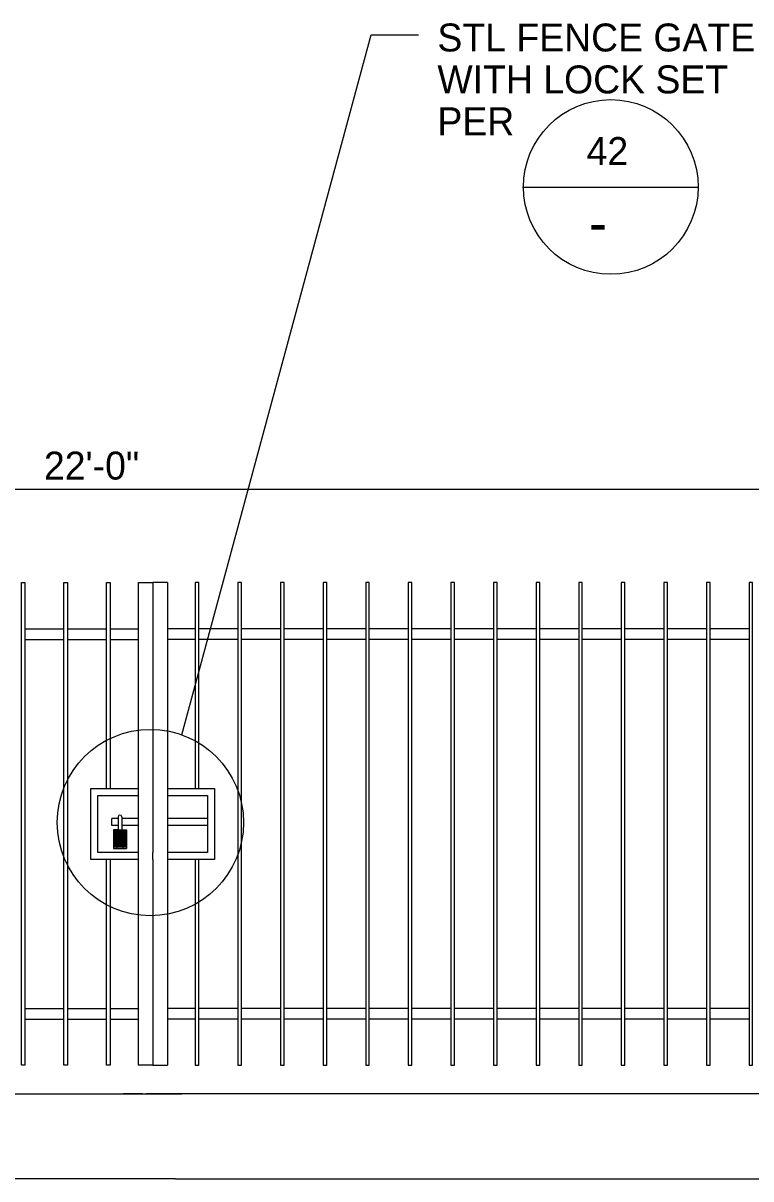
# Model space of a CAD drawing. Extents: x -121933 to -117742, y -103160 to -100084.
# Drawn here: x -118656.4 to -118500.2, y -103076 to -102827.9 of the extents above; entities that cross this region are included whole.
import ezdxf

# ---------------------------------------------------------------- set-up
doc = ezdxf.new("R2010")
doc.units = 0
doc.layers.add('G-MARK', color=7, linetype='Continuous')
doc.layers.add('Misc CnstDet(22)', color=7, linetype='Continuous')

msp = doc.modelspace()

# ---------------------------------------------------------------- linework, layer by layer
at = {"layer": 'G-MARK'}
for p, q in [((-118622.3, -102980.66), (-118581.66, -102830.38)), ((-118581.66, -102830.38), (-118571.52, -102830.38)), ((-118549.17, -102863.09), (-118511.47, -102863.09)), ((-118800.69, -102927.94), (-118459.12, -102927.94)), ((-118800.69, -102927.94), (-118456.45, -102927.94))]:
    msp.add_line(p, q, dxfattribs=at)
msp.add_lwpolyline([(-118618.64, -102992.18), (-118618.64, -102947.98), (-118619.41, -102947.98), (-118619.41, -102992.18)], dxfattribs=at)
for centre, radius in [((-118530.22, -102863.04), 18.75), ((-118629.06, -102999.49), 20)]:
    msp.add_circle(centre, radius, dxfattribs=at)
at = {"layer": 'Misc CnstDet(22)'}
for p, q in [((-118631.7, -102947.98), (-118631.7, -103007.42)), ((-118631.7, -102947.98), (-118628.55, -102947.98)), ((-118625.41, -102947.98), (-118628.55, -102947.98)), ((-118628.55, -102947.98), (-118628.55, -102992.18)), ((-118628.55, -102947.98), (-118628.55, -102992.18)), ((-118625.41, -102947.98), (-118625.41, -103007.42)), ((-118655.99, -102957.89), (-118647.61, -102957.89)), ((-118646.85, -102957.89), (-118638.47, -102957.89)), ((-118637.7, -102957.89), (-118633.07, -102957.89)), ((-118633.07, -102957.89), (-118631.7, -102957.89)), ((-118624.04, -102957.89), (-118625.41, -102957.89)), ((-118619.41, -102957.89), (-118624.04, -102957.89)), ((-118610.26, -102957.89), (-118618.64, -102957.89)), ((-118601.12, -102957.89), (-118609.5, -102957.89)), ((-118591.97, -102957.89), (-118600.36, -102957.89)), ((-118582.83, -102957.89), (-118591.21, -102957.89)), ((-118573.69, -102957.89), (-118582.07, -102957.89)), ((-118564.54, -102957.89), (-118572.92, -102957.89)), ((-118555.4, -102957.89), (-118563.78, -102957.89)), ((-118546.25, -102957.89), (-118554.64, -102957.89)), ((-118537.11, -102957.89), (-118545.49, -102957.89)), ((-118527.97, -102957.89), (-118536.35, -102957.89)), ((-118518.82, -102957.89), (-118527.2, -102957.89)), ((-118509.68, -102957.89), (-118518.06, -102957.89)), ((-118500.53, -102957.89), (-118508.92, -102957.89)), ((-118655.99, -102960.17), (-118647.61, -102960.17)), ((-118646.85, -102960.17), (-118638.47, -102960.17)), ((-118637.7, -102960.17), (-118631.7, -102960.17)), ((-118619.41, -102960.17), (-118625.41, -102960.17)), ((-118610.26, -102960.17), (-118618.64, -102960.17)), ((-118601.12, -102960.17), (-118609.5, -102960.17)), ((-118591.97, -102960.17), (-118600.36, -102960.17)), ((-118582.83, -102960.17), (-118591.21, -102960.17)), ((-118573.69, -102960.17), (-118582.07, -102960.17)), ((-118564.54, -102960.17), (-118572.92, -102960.17)), ((-118555.4, -102960.17), (-118563.78, -102960.17)), ((-118546.25, -102960.17), (-118554.64, -102960.17)), ((-118537.11, -102960.17), (-118545.49, -102960.17)), ((-118527.97, -102960.17), (-118536.35, -102960.17)), ((-118518.82, -102960.17), (-118527.2, -102960.17)), ((-118509.68, -102960.17), (-118518.06, -102960.17)), ((-118500.53, -102960.17), (-118508.92, -102960.17)), ((-118641.85, -103007.42), (-118641.85, -102992.18)), ((-118641.85, -102992.18), (-118631.7, -102992.18)), ((-118628.55, -102992.18), (-118628.55, -103005.92)), ((-118625.41, -102992.18), (-118615.26, -102992.18)), ((-118615.26, -102992.18), (-118615.26, -103007.42)), ((-118640.35, -103005.92), (-118640.35, -102993.68)), ((-118640.35, -102993.68), (-118631.7, -102993.68)), ((-118625.41, -102993.68), (-118616.76, -102993.68)), ((-118616.76, -102993.68), (-118616.76, -103005.92)), ((-118637.3, -103000.14), (-118637.3, -102998.64)), ((-118635.95, -102998.64), (-118637.3, -102998.64)), ((-118635.95, -103000.14), (-118637.3, -103000.14)), ((-118635.95, -102998.27), (-118635.95, -103001.06)), ((-118635.2, -102998.27), (-118635.2, -103001.06)), ((-118631.7, -102998.64), (-118635.2, -102998.64)), ((-118631.7, -103000.14), (-118635.2, -103000.14)), ((-118616.76, -102998.64), (-118625.41, -102998.64)), ((-118616.76, -103000.14), (-118625.41, -103000.14)), ((-118635.95, -103001.06), (-118636.95, -103001.06)), ((-118636.95, -103001.06), (-118636.95, -103005.06)), ((-118634.2, -103001.31), (-118636.95, -103001.31)), ((-118634.2, -103001.56), (-118636.95, -103001.56)), ((-118634.2, -103001.81), (-118636.95, -103001.81)), ((-118634.2, -103002.06), (-118636.95, -103002.06)), ((-118634.2, -103002.31), (-118636.95, -103002.31)), ((-118634.2, -103002.56), (-118636.95, -103002.56)), ((-118636.24, -103001.06), (-118636.24, -103005.06)), ((-118635.95, -103001.06), (-118635.2, -103001.06)), ((-118635.2, -103001.06), (-118634.2, -103001.06)), ((-118634.97, -103001.06), (-118634.97, -103005.06)), ((-118634.2, -103001.06), (-118634.2, -103005.06)), ((-118634.2, -103002.81), (-118636.95, -103002.81)), ((-118634.2, -103003.06), (-118636.95, -103003.06)), ((-118634.2, -103003.31), (-118636.95, -103003.31)), ((-118634.2, -103003.56), (-118636.95, -103003.56)), ((-118634.2, -103003.81), (-118636.95, -103003.81)), ((-118634.2, -103004.06), (-118636.95, -103004.06)), ((-118634.2, -103004.31), (-118636.95, -103004.31)), ((-118634.2, -103004.56), (-118636.95, -103004.56)), ((-118634.2, -103004.81), (-118636.95, -103004.81)), ((-118636.95, -103005.06), (-118634.2, -103005.06)), ((-118631.7, -103007.42), (-118641.85, -103007.42)), ((-118631.7, -103005.92), (-118640.35, -103005.92)), ((-118631.7, -103007.42), (-118631.7, -103051.61)), ((-118628.55, -103007.42), (-118628.55, -103005.92)), ((-118616.76, -103005.92), (-118625.41, -103005.92)), ((-118625.41, -103007.42), (-118625.41, -103051.61)), ((-118615.26, -103007.42), (-118625.41, -103007.42)), ((-118655.99, -103039.42), (-118647.61, -103039.42)), ((-118646.85, -103039.42), (-118638.47, -103039.42)), ((-118637.7, -103039.42), (-118631.7, -103039.42)), ((-118619.41, -103039.42), (-118625.41, -103039.42)), ((-118610.26, -103039.42), (-118618.64, -103039.42)), ((-118601.12, -103039.42), (-118609.5, -103039.42)), ((-118591.97, -103039.42), (-118600.36, -103039.42)), ((-118582.83, -103039.42), (-118591.21, -103039.42)), ((-118573.69, -103039.42), (-118582.07, -103039.42)), ((-118564.54, -103039.42), (-118572.92, -103039.42)), ((-118555.4, -103039.42), (-118563.78, -103039.42)), ((-118546.25, -103039.42), (-118554.64, -103039.42)), ((-118537.11, -103039.42), (-118545.49, -103039.42)), ((-118527.97, -103039.42), (-118536.35, -103039.42)), ((-118518.82, -103039.42), (-118527.2, -103039.42)), ((-118509.68, -103039.42), (-118518.06, -103039.42)), ((-118500.53, -103039.42), (-118508.92, -103039.42)), ((-118655.99, -103041.71), (-118647.61, -103041.71)), ((-118646.85, -103041.71), (-118638.47, -103041.71)), ((-118637.7, -103041.71), (-118631.7, -103041.71)), ((-118619.41, -103041.71), (-118625.41, -103041.71)), ((-118610.26, -103041.71), (-118618.64, -103041.71)), ((-118601.12, -103041.71), (-118609.5, -103041.71)), ((-118591.97, -103041.71), (-118600.36, -103041.71)), ((-118582.83, -103041.71), (-118591.21, -103041.71)), ((-118573.69, -103041.71), (-118582.07, -103041.71)), ((-118564.54, -103041.71), (-118572.92, -103041.71)), ((-118555.4, -103041.71), (-118563.78, -103041.71)), ((-118546.25, -103041.71), (-118554.64, -103041.71)), ((-118537.11, -103041.71), (-118545.49, -103041.71)), ((-118527.97, -103041.71), (-118536.35, -103041.71)), ((-118518.82, -103041.71), (-118527.2, -103041.71)), ((-118509.68, -103041.71), (-118518.06, -103041.71)), ((-118500.53, -103041.71), (-118508.92, -103041.71)), ((-118628.55, -103051.61), (-118631.7, -103051.61)), ((-118628.55, -103051.61), (-118625.41, -103051.61)), ((-118795.1, -103057.71), (-118622.28, -103057.71)), ((-118630.75, -103057.71), (-118634.83, -103057.71)), ((-118462.01, -103057.71), (-118629.99, -103057.71)), ((-118623.66, -103076), (-118795.1, -103076)), ((-118623.66, -103076), (-118462.01, -103076))]:
    msp.add_line(p, q, dxfattribs=at)
for points in [[(-118655.99, -103051.61), (-118656.75, -103051.61), (-118656.75, -102947.98), (-118655.99, -102947.98)], [(-118646.85, -103051.61), (-118647.61, -103051.61), (-118647.61, -102947.98), (-118646.85, -102947.98)], [(-118610.26, -103051.61), (-118609.5, -103051.61), (-118609.5, -102947.98), (-118610.26, -102947.98)], [(-118601.12, -103051.61), (-118600.36, -103051.61), (-118600.36, -102947.98), (-118601.12, -102947.98)], [(-118591.97, -103051.61), (-118591.21, -103051.61), (-118591.21, -102947.98), (-118591.97, -102947.98)], [(-118582.83, -103051.61), (-118582.07, -103051.61), (-118582.07, -102947.98), (-118582.83, -102947.98)], [(-118573.69, -103051.61), (-118572.92, -103051.61), (-118572.92, -102947.98), (-118573.69, -102947.98)], [(-118564.54, -103051.61), (-118563.78, -103051.61), (-118563.78, -102947.98), (-118564.54, -102947.98)], [(-118555.4, -103051.61), (-118554.64, -103051.61), (-118554.64, -102947.98), (-118555.4, -102947.98)], [(-118546.25, -103051.61), (-118545.49, -103051.61), (-118545.49, -102947.98), (-118546.25, -102947.98)], [(-118537.11, -103051.61), (-118536.35, -103051.61), (-118536.35, -102947.98), (-118537.11, -102947.98)], [(-118527.97, -103051.61), (-118527.2, -103051.61), (-118527.2, -102947.98), (-118527.97, -102947.98)], [(-118518.82, -103051.61), (-118518.06, -103051.61), (-118518.06, -102947.98), (-118518.82, -102947.98)], [(-118509.68, -103051.61), (-118508.92, -103051.61), (-118508.92, -102947.98), (-118509.68, -102947.98)], [(-118500.53, -103051.61), (-118499.77, -103051.61), (-118499.77, -102947.98), (-118500.53, -102947.98)]]:
    msp.add_lwpolyline(points, close=True, dxfattribs=at)
for points in [[(-118638.47, -102992.18), (-118638.47, -102947.98), (-118637.7, -102947.98), (-118637.7, -102992.18)], [(-118637.7, -103051.61), (-118638.47, -103051.61), (-118638.47, -103007.42)], [(-118637.7, -103007.42), (-118637.7, -103051.61)], [(-118628.55, -103007.42), (-118628.55, -103051.61)], [(-118628.55, -103007.42), (-118628.55, -103051.61)], [(-118619.41, -103051.61), (-118618.64, -103051.61), (-118618.64, -103007.42)], [(-118619.41, -103007.42), (-118619.41, -103051.61)]]:
    msp.add_lwpolyline(points, dxfattribs=at)
for start, end in [(0.004, 180), (359.996, 0)]:
    msp.add_arc((-118635.58, -102998.27), 0.375, start, end, dxfattribs=at)

# ---------------------------------------------------------------- texts
at = {"layer": 'G-MARK'}
msp.add_text('-', height=8.75, dxfattribs=at).set_placement((-118534.94, -102875.08))
at = {"layer": 'Misc CnstDet(22)'}
for s, p in [('STL FENCE GATE', (-118567.44, -102833.95)), ('WITH LOCK SET', (-118567.44, -102842.95)), ('PER', (-118567.44, -102851.95)), ('42', (-118535.41, -102858.33)), ('22\'-0"', (-118651.9, -102925.86))]:
    msp.add_text(s, height=6, dxfattribs=at).set_placement(p)

doc.saveas('drawing.dxf')
